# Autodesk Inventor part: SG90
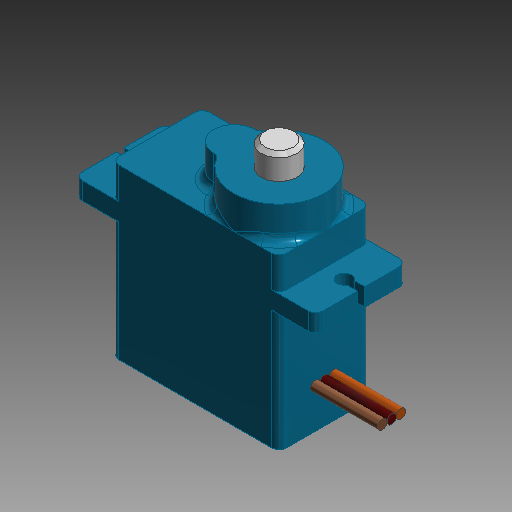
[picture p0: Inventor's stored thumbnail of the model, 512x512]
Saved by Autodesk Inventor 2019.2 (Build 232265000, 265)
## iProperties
Part Number: SG90
Material: ABS Plastic
Document SubType Name: Modeling
Designer: richard.girt
Mass: 7.54185 g
Surface Area: 27.447 cm^2
Volume: 7.11495 cm^3
Density: 1.06 g/cm^3
Appearance: Smooth - White
Author: richard.girt
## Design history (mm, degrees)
sketch "Sketch1"
  geometry: L1 (-11.25, -6.1)-(11.25, -6.1); L2 (11.25, -6.1)-(11.25, 6.1); L3 (11.25, 6.1)-(-11.25, 6.1); L4 (-11.25, 6.1)-(-11.25, -6.1); L5 (-11.25, -6.1)-(11.25, 6.1); L6 (11.25, -6.1)-(-11.25, 6.1); 1 further point
  constraints: 12 end point, 2 midpoint, 2 parallel, 1 horizontal, 1 perpendicular
  dimensions: "d0" = 22.5 distance of L2.end L3.end; "d1" = 12.2 distance of L3.end L1.start
extrude "Extrusion1" new body sketch "Sketch1" distance "d2" = 16; taper "d3" = 0 deg
sketch "Sketch2"
  geometry: L1 (16.15, -6.1)-(-16.15, -6.1); L2 (-16.15, -6.1)-(-16.15, 6.1); L3 (-16.15, 6.1)-(16.15, 6.1); L4 (16.15, 6.1)-(16.15, -6.1); L5 (16.15, -6.1)-(-16.15, 6.1); L6 (-16.15, -6.1)-(16.15, 6.1); 2 further points
  constraints: 12 end point, 2 midpoint, 2 parallel, 1 horizontal, 1 perpendicular, 1 point on line
  dimensions: "d4" = 32.3 distance of L1.start L1.end
extrude "Extrusion2" join sketch "Sketch2" distance "d5" = 2.36; taper "d6" = 0 deg
sketch "Sketch3"
  geometry: L1 (-11.25, 6.1)-(11.25, 6.1) reference; L2 (11.25, 6.1)-(11.25, -6.1) reference; L3 (11.25, -6.1)-(-11.25, -6.1) reference; L4 (-11.25, -6.1)-(-11.25, 6.1) reference; L5 (-11.25, -6.1)-(11.25, -6.1); L6 (11.25, -6.1)-(11.25, 6.1); L7 (11.25, 6.1)-(-11.25, 6.1); L8 (-11.25, 6.1)-(-11.25, -6.1); L9 (-11.25, -6.1)-(11.25, 6.1); L10 (11.25, -6.1)-(-11.25, 6.1); 1 further point
  constraints: 12 end point, 2 midpoint, 2 parallel, 1 horizontal, 1 perpendicular
extrude "Extrusion3" join sketch "Sketch3" distance "d7" = 4.25; taper "d8" = 0 deg
sketch "Sketch4"
  geometry: L1 (11.25, -6.1)-(11.25, 6.1) reference; L2 (11.25, 6.1)-(-11.25, 6.1) reference; L3 (-11.25, -6.1)-(11.25, -6.1) reference; C1 r 6.1 at (5.15, 0); C2 r 2.75 at (-0.85, 0); 1 further point
  constraints: 3 tangent, 2 centre point, 1 horizontal alignment
  dimensions: "d9" = 5.5 diameter of C2; "d10" = 6 distance of C2.centre C1.centre
extrude "Extrusion4" join sketch "Sketch4" distance "d11" = 4.4; taper "d12" = 0 deg
sketch "Sketch5"
  geometry: C1 r 2.4 at (5.15, 0); A1 r 6.1 centre (5.15, 0) between (-0.321, -2.699) and (-0.321, 2.699) reference; 1 further point
  constraints: 1 centre point, 1 coincident
  dimensions: "d13" = 4.8 diameter of C1
extrude "Extrusion5" new body sketch "Sketch5" distance "d14" = 3.26; taper "d15" = 0 deg
chamfer "Chamfer1" distance "d16" = 0.5; stored, may be unused: second distance "d17" = 2, angle "d18" = 45 deg
sketch "Sketch6"
  geometry: L1 (-16.15, 6.1)-(-16.15, -6.1) reference; L2 (-13.9, 0)-(13.9, 0); L3 (-14.766, 0.5)-(-16.15, 0.5); L4 (-16.15, 0.5)-(-16.15, -0.5); L5 (-16.15, -0.5)-(-14.766, -0.5); L6 (-14.766, -0.5)-(-14.766, 0.5); L7 (-14.766, 0.5)-(-16.15, -0.5); L8 (-16.15, 0.5)-(-14.766, -0.5); L9 (16.15, 6.1)-(16.15, -6.1) reference; L10 (14.766, -0.5)-(16.15, -0.5); L11 (16.15, -0.5)-(16.15, 0.5); L12 (16.15, 0.5)-(14.766, 0.5); L13 (14.766, 0.5)-(14.766, -0.5); L14 (14.766, -0.5)-(16.15, 0.5); L15 (16.15, -0.5)-(14.766, 0.5); A1 r 1 centre (-13.9, 0) between (-14.766, 0.5) and (-14.766, -0.5); A2 r 1 centre (13.9, 0) between (14.766, 0.5) and (14.766, -0.5); 4 further points
  constraints: 26 end point, 5 midpoint, 5 parallel, 4 point on circle, 3 coincident, 3 horizontal, 2 centre point, 2 perpendicular, 2 point on line, 1 equal radius
  dimensions: "d19" = 27.8 distance of L2.start L2.end; "d20" = 2 diameter of A1; "d21" = 1 distance between parallel lines of L5 L3
extrude "Extrusion6" cut sketch "Sketch6" extent not by distance; stored distance "d22" = 3.26; taper "d23" = 0 deg
fillet "Fillet1" dims "d24" = 1
sketch "Sketch7"
  geometry: L1 (0, 16)-(0, 0) reference; L2 (0, 0)-(-10.2, 0) reference; L3 (-10.2, 16)-(-10.2, 0) reference; L4 (-10.2, 5.3)-(0, 5.3); C1 r 0.625 at (-5.1, 5.3); C2 r 0.625 at (-3.85, 5.3); C3 r 0.625 at (-6.35, 5.3); 1 further point
  constraints: 4 equal radius, 4 point on line, 3 centre point, 2 end point, 1 midpoint, 1 perpendicular
  dimensions: "d25" = 5.3 distance between parallel lines of L4 L2; "d26" = 1.25 diameter of C2
extrude "Extrusion7" new body sketch "Sketch7" distance "d27" = 9; taper "d28" = 0 deg
body "Solid1"
node "Projected Loop1"
body "Solid2"
body "Solid3"
other parameters: "d29" = 0
